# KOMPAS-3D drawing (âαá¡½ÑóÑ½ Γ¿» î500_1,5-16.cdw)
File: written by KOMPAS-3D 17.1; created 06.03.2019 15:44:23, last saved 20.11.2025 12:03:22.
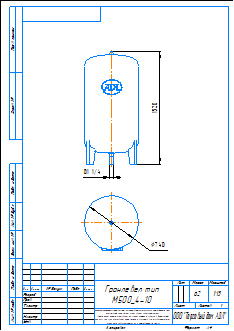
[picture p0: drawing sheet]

Sheet 1: A4, portrait

Title block, sheet 1: name: Гранлевел тип / М500_4-10; mass: 62; sheets: 1; sheet format: A4; stored path: C:\Users\kka\KOMPAS_Work\!Trash\ГРАНЛЕВЕЛ тип А Расширительный бак\KOMPAS 2D\Гранлевел тип А100_1,5-16.cdw

Views: Спереди 1, Спереди, Проекционный вид 2
Referenced files in C:\Users\mipv\Desktop\Тип А\SAT\: Гранлевел тип А500_4-10.a3d
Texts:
  kka
  adl
  Гранлевел тип А500_4-10
  Рама для чертежей
  Лит-Масса-Масштаб
  Материал-Предприятие
  Масштаб
  Изм.
  Лист
  № докум.
  Подп.
  Дата
  Лит.
  Разраб.
  Пров.
  Т.контр.
  Листов
  Внимание! Данный продукт является объектом авторского права ООО «Торговый Дом АДЛ».
  Запрещается изменение, копирование, распространение
  (в том числе путем копирования на другие сайты и ресурсы в Интернете)
  или любое иное использование информации и объектов без предварительного
  согласия правообладателя (ООО «Торговый Дом АДЛ»).
  Н.контр.
  Утв.
  ООО "Торговый дом АДЛ"
  Изменение
  Номер документа
  Подпись
  Обозначение документа
  Наименование изделия
  Масса изделия по ГОСТ 2.109-73
  Порядковый номер листа
  Общее количество листов в документе
  Характер работы, выполненной лицом, подписавшим документ
  Наименование или индекс предприятия, выпускающего документ
  Инв. № подл.
  Подп. и дата
  Взам. инв. №
  Инв. № дубл.
  Инвентарный номер подлинника по ГОСТ 2.501-68
  Подпись принявшего подлинник в отдел технической документации
  Инвентарный номер подлинника, взамен которого выпущен данный подлинник
  Инвентарный номер дубликата по ГОСТ 2.502-68
  Подпись принявшего дубликат в отдел технической документации
  Справ. №
  Перв. примен.
  Обозначение документа, взамен или на основании которого выпущен данный документ
  Обозначение документа, в котором впервые записан данный документ
  Подпись лица, копировавшего чертеж
  Обозначение формата листа
  !Рама для чертежа
Dimensions and other numbers on the sheet: 1520; 740; 1:15; 1; 62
